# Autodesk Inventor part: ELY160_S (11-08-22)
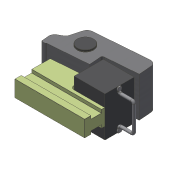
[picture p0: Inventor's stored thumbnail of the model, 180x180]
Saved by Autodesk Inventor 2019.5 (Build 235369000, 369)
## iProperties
Created: 2022-08
Part Number: ELY160_S (11-08-22)
Material: St37-2 / S235
Document SubType Name: Modeling
Designer: schoth
Density: 7.86 g/cm^3
Appearance: Steel
RuleStatus: InUse
Author: schoth
Mass(KG): 0.0
Area(mm): 0.0
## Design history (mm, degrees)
derived "ELY160.iam"
body "Solid1"
node "FB215-005.ipt:1"
node "ELY160-88.iam:1::FB219-030.ipt:1"
node "ELY160-88.iam:1::FB393-070.ipt:1"
node "ELY160-99.iam:1::FB216-011.ipt:1"
node "ELY160-99.iam:1::FB217-104.ipt:1"
node "ELY160.iam_Bodies"
